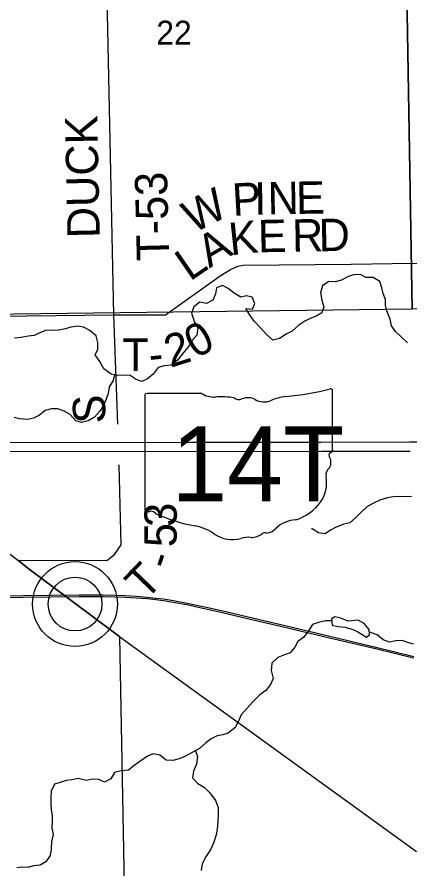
# Model space of a CAD drawing. Extents: x 0 to 34, y 0 to 22.
# Drawn here: x 2.754 to 3.443, y 18.256 to 19.751 of the extents above; entities that cross this region are included whole.
import ezdxf

# ---------------------------------------------------------------- set-up
doc = ezdxf.new("R2010")
doc.units = 0
for name, color, linetype in [('GM_X_County_Road', 7, 'Continuous'), ('GM_X_Minor_Lake', 7, 'Continuous'), ('GM_X_Minor_River', 7, 'Continuous'), ('GM_X_Rail_Line', 7, 'Continuous'), ('GM_X_Section', 7, 'Continuous'), ('GM_X_Section_Text', 7, 'Continuous'), ('GM_X_State_Location', 7, 'Continuous'), ('GM_X_State_Route', 7, 'Continuous'), ('GM_X_State_Shield', 7, 'Continuous'), ('GM_X_Township_Road', 7, 'Continuous'), ('GM_X_Township_Road_Text', 7, 'Continuous'), ('GM_X_Unincorporated', 7, 'Continuous'), ('GM_X_Unincorporated_Location', 7, 'Continuous')]:
    doc.layers.add(name, color=color, linetype=linetype)

msp = doc.modelspace()

# ---------------------------------------------------------------- linework, layer by layer
at = {"layer": 'GM_X_County_Road'}
msp.add_line((2.1794, 19.2202), (2.9238, 19.2285), dxfattribs=at)
at = {"layer": 'GM_X_Minor_Lake'}
for points in [[(3.3519, 18.6725), (3.3671, 18.6628), (3.3724, 18.6674), (3.3719, 18.6765), (3.3631, 18.687), (3.3525, 18.6926), (3.3347, 18.6913), (3.3221, 18.6965), (3.3115, 18.6984), (3.3059, 18.6949), (3.3071, 18.6843), (3.3166, 18.6817), (3.3302, 18.6807)], [(3.3302, 18.6807), (3.3347, 18.6791), (3.3395, 18.6777), (3.3448, 18.6758), (3.3495, 18.6737), (3.3519, 18.6725)]]:
    msp.add_lwpolyline(points, dxfattribs=at)
at = {"layer": 'GM_X_Minor_River'}
for points in [[(3.4392, 19.1791), (3.4281, 19.19), (3.4182, 19.1994), (3.4113, 19.2092), (3.4085, 19.2209), (3.4027, 19.2357), (3.4003, 19.2456), (3.4006, 19.2554), (3.3964, 19.266), (3.394, 19.2759), (3.3905, 19.2869), (3.3787, 19.294), (3.3662, 19.2939), (3.3567, 19.2991), (3.3449, 19.2986), (3.3351, 19.2955), (3.3231, 19.289), (3.3121, 19.2862), (3.3011, 19.2869), (3.2899, 19.2792), (3.2866, 19.2678), (3.289, 19.2541), (3.2921, 19.2427), (3.2888, 19.2317), (3.2786, 19.2259), (3.2684, 19.222), (3.2586, 19.2174), (3.2485, 19.2101), (3.2365, 19.1997), (3.2259, 19.1947), (3.2142, 19.187), (3.2025, 19.1842), (3.1911, 19.1944), (3.1815, 19.2053), (3.17, 19.2174), (3.1616, 19.2287), (3.1554, 19.2393), (3.1668, 19.2382), (3.1709, 19.2485), (3.1662, 19.2595), (3.1564, 19.2617), (3.1466, 19.2593), (3.1347, 19.2665), (3.1245, 19.2747), (3.1142, 19.2796), (3.1036, 19.2757), (3.1018, 19.265), (3.0974, 19.254), (3.0861, 19.2482), (3.0747, 19.2504), (3.0642, 19.2423), (3.0601, 19.2313), (3.0652, 19.2154), (3.0713, 19.2055), (3.0692, 19.1926), (3.0606, 19.1827), (3.0546, 19.1727), (3.0441, 19.1597), (3.0351, 19.149), (3.0246, 19.1402), (3.0118, 19.1389), (3.0016, 19.1358), (2.9926, 19.1243), (2.9824, 19.1159), (2.9726, 19.1113), (2.9628, 19.115), (2.9521, 19.1221), (2.9407, 19.1224), (2.9294, 19.1219), (2.9191, 19.1241), (2.9062, 19.1339), (2.8989, 19.1463), (2.8908, 19.158), (2.8953, 19.1683), (2.8955, 19.1797), (2.8928, 19.1915), (2.8813, 19.2009), (2.8703, 19.2068), (2.8608, 19.2083), (2.8483, 19.2067), (2.8385, 19.2039), (2.8264, 19.2015), (2.8158, 19.2011), (2.8052, 19.2014), (2.795, 19.1975), (2.7837, 19.1921), (2.7731, 19.1908), (2.761, 19.1888), (2.7489, 19.1876)], [(2.9247, 19.1229), (2.9226, 19.1131), (2.9156, 19.1024), (2.9134, 19.0903), (2.9101, 19.0803), (2.9053, 19.0693), (2.8989, 19.0594), (2.8899, 19.0487), (2.8783, 19.0425), (2.8669, 19.0393), (2.8567, 19.0423), (2.8471, 19.0536), (2.8365, 19.0596), (2.8251, 19.0637), (2.8141, 19.0636), (2.8031, 19.0604), (2.793, 19.0524), (2.7824, 19.047), (2.7718, 19.045), (2.7582, 19.046), (2.7487, 19.0482)], [(3.4459, 18.9095), (3.4349, 18.9094), (3.4243, 18.9097), (3.4141, 18.9092), (3.4042, 18.9072), (3.3906, 18.9033), (3.3782, 18.8975), (3.3677, 18.8914), (3.3571, 18.8818), (3.3478, 18.8722), (3.3376, 18.8634), (3.3274, 18.861), (3.3138, 18.856), (3.3041, 18.8506), (3.2943, 18.844), (3.2829, 18.8462), (3.2715, 18.8529), (3.2703, 18.8529)], [(3.3062, 18.6917), (3.2953, 18.6918), (3.2828, 18.6886), (3.2726, 18.6851), (3.2652, 18.6744), (3.2569, 18.6633), (3.2468, 18.6553), (3.2416, 18.6457), (3.2334, 18.6354), (3.2232, 18.6323), (3.2115, 18.6273), (3.201, 18.6173), (3.1996, 18.6047), (3.2031, 18.5907), (3.1987, 18.5801), (3.1904, 18.5697), (3.1799, 18.5617), (3.1675, 18.5494), (3.1574, 18.5387), (3.1469, 18.5268), (3.1425, 18.5154), (3.1365, 18.5043), (3.1245, 18.4944), (3.1147, 18.492), (3.1048, 18.49), (3.0947, 18.4846), (3.0849, 18.4777), (3.074, 18.4677), (3.0623, 18.4612), (3.0484, 18.4539), (3.0382, 18.4496), (3.0269, 18.4468), (3.0155, 18.4471), (3.0041, 18.4561), (2.9927, 18.4583), (2.9829, 18.4544), (2.9694, 18.4448), (2.9592, 18.4379), (2.9494, 18.4298), (2.9366, 18.4286), (2.9249, 18.4255), (2.9185, 18.4148), (2.9072, 18.4086), (2.897, 18.4131), (2.886, 18.4137), (2.8758, 18.4117), (2.861, 18.415), (2.85, 18.413), (2.8398, 18.4118), (2.8296, 18.4079), (2.8194, 18.4052), (2.8135, 18.393), (2.8128, 18.3812), (2.8129, 18.371), (2.8138, 18.36), (2.815, 18.3501), (2.8155, 18.3398), (2.8148, 18.3285), (2.8172, 18.3167), (2.8143, 18.3049), (2.8137, 18.2909), (2.8119, 18.2798), (2.8044, 18.2691), (2.7942, 18.263), (2.7825, 18.2621), (2.7727, 18.259), (2.7628, 18.2597), (2.753, 18.2584)], [(3.4499, 18.651), (3.4395, 18.6539), (3.4296, 18.6572), (3.4187, 18.6567), (3.4077, 18.6544), (3.3963, 18.6584), (3.386, 18.6671), (3.3742, 18.6712), (3.3722, 18.6712)], [(3.0667, 18.4637), (3.0707, 18.454), (3.0686, 18.4404), (3.0634, 18.4282), (3.0616, 18.416), (3.0712, 18.4062), (3.0826, 18.3991), (3.0921, 18.3897), (3.1021, 18.3765), (3.1068, 18.3644), (3.1069, 18.3515), (3.1062, 18.3393), (3.1052, 18.3264), (3.1034, 18.3161), (3.099, 18.3032), (3.0938, 18.2914), (3.0856, 18.2791), (3.0789, 18.2654), (3.0771, 18.2536)]]:
    msp.add_lwpolyline(points, dxfattribs=at)
at = {"layer": 'GM_X_Rail_Line'}
for points in [[(2.1, 18.7305), (2.109, 18.7306), (2.2199, 18.7315), (2.2909, 18.7321), (2.5385, 18.7345), (2.6658, 18.7351), (2.8628, 18.737), (2.885, 18.7371), (2.9051, 18.7371), (2.9252, 18.7366), (2.9432, 18.736), (2.9628, 18.7349), (2.9815, 18.7334), (2.9975, 18.7316), (3.0109, 18.73), (3.0284, 18.7273), (3.0523, 18.7229), (3.0854, 18.7157), (3.1127, 18.7096), (3.1492, 18.701), (3.2266, 18.6828), (3.3027, 18.6648), (3.3835, 18.6457), (3.4502, 18.6294)], [(2.1, 18.7277), (2.109, 18.7278), (2.22, 18.7287), (2.291, 18.7293), (2.5385, 18.7317), (2.6658, 18.7323), (2.8628, 18.7342), (2.885, 18.7343), (2.9051, 18.7343), (2.9251, 18.7338), (2.9431, 18.7332), (2.9626, 18.7321), (2.9812, 18.7306), (2.9972, 18.7288), (3.0106, 18.7273), (3.028, 18.7245), (3.0517, 18.7201), (3.0848, 18.713), (3.1121, 18.7069), (3.1485, 18.6983), (3.2259, 18.6801), (3.302, 18.6621), (3.3829, 18.643), (3.4495, 18.6266)]]:
    msp.add_lwpolyline(points, dxfattribs=at)
at = {"layer": 'GM_X_Section'}
for points in [[(4.4904, 20.2497), (4.497, 19.2557), (3.4475, 19.2384), (3.4305, 20.2427)], [(3.4305, 20.2427), (3.4475, 19.2384), (2.4219, 19.2256), (2.4052, 20.2337)]]:
    msp.add_lwpolyline(points, close=True, dxfattribs=at)
at = {"layer": 'GM_X_State_Route'}
for p, q in [((2.5408, 18.9623), (2.7549, 18.7978)), ((2.9341, 18.6634), (3.4547, 18.2871))]:
    msp.add_line(p, q, dxfattribs=at)
for points in [[(3.4435, 19.0056), (3.6553, 19.0056), (3.8845, 19.0061), (4.1596, 19.0061), (4.3747, 19.0061), (4.4833, 19.0063), (4.6257, 19.0064), (4.836, 19.0077), (4.9952, 19.0069), (5.1872, 19.0079)], [(2.5272, 18.972), (2.5405, 18.9799), (2.559, 18.9878), (2.5794, 18.9942), (2.6031, 18.9999), (2.6253, 19.0033), (2.6524, 19.0044), (2.6855, 19.0045), (3.0584, 19.0051), (3.2872, 19.0053), (3.4435, 19.0056)], [(2.5408, 18.9623), (2.5572, 18.9723), (2.5755, 18.9799), (2.5961, 18.986), (2.6168, 18.9872), (2.6691, 18.989), (3.059, 18.9887), (3.2874, 18.989), (3.4437, 18.9894)], [(2.7549, 18.7978), (2.7692, 18.7867), (2.7725, 18.7843)], [(2.7725, 18.7843), (2.927, 18.6687), (2.9341, 18.6634)]]:
    msp.add_lwpolyline(points, dxfattribs=at)
at = {"layer": 'GM_X_State_Shield'}
for p, q in [((2.978, 19.087), (2.978, 18.8869)), ((3.0778, 19.0905), (2.9812, 19.0905)), ((3.3076, 18.9907), (3.3076, 19.0954)), ((3.3075, 18.9908), (3.3076, 18.9907))]:
    msp.add_line(p, q, dxfattribs=at)
for centre, major_axis, start_param, end_param in [((3.1902, 19.3633), (0.3495, 0), 4.814394, 5.042369), ((3.3039, 19.0958), (0.00367, 0), 6.141152, 7.989035), ((2.9818, 19.0874), (0.00382, 0), 1.712693, 3.28349), ((3.1007, 19.1137), (0.037, 0), 4.042523, 4.731795), ((3.113, 18.9781), (0.133, 0), 1.404758, 1.657858), ((3.1432, 19.0885), (0.0107, 0), 3.836095, 5.185415), ((3.1589, 19.0653), (0.0222, 0), 0.950623, 2.079405), ((3.2348, 19.0293), (0.0703, 0), 1.699011, 2.107814), ((3.1876, 19.0971), (0.0267, 0), 4.081561, 5.145723), ((3.3067, 18.983), (0.00568, 0), 1.883978, 3.671073), ((3.2706, 18.9698), (0.0341, 0), 5.934695, 6.695948), ((3.3037, 18.9903), (0.00393, 0), 5.05454, 6.418171), ((3.3207, 18.9469), (0.0248, 0), 2.387724, 3.262537), ((3.2098, 18.9336), (0.0874, 0), 5.101752, 6.440018), ((2.9818, 18.8865), (0.00385, 0), 3.00124, 4.508301), ((2.9824, 18.9069), (0.0294, 0), 4.665946, 4.897461), ((2.9884, 18.8753), (0.0106, 0), 0.519207, 1.627899), ((3.1222, 19.0551), (0.2524, 0), 4.195997, 4.488961), ((3.047, 18.797), (0.079, 0), 0.823519, 1.323587), ((3.2466, 18.8307), (0.0479, 0), 1.647645, 2.488434), ((3.1324, 18.8744), (0.0501, 0), 4.026481, 4.996735), ((3.165, 18.8594), (0.0267, 0), 4.691044, 5.507374), ((3.1892, 18.84), (0.00752, 0), 1.147584, 2.315152), ((3.186, 18.8675), (0.0282, 0), 4.937069, 5.64225), ((3.1613, 18.8052), (0.0412, 0), 1.495662, 1.94098)]:
    msp.add_ellipse(centre, major_axis=major_axis, ratio=0.8, start_param=start_param, end_param=end_param, dxfattribs=at)
at = {"layer": 'GM_X_Township_Road'}
for p, q in [((2.9238, 19.2285), (2.9018, 20.2384)), ((2.9306, 19.0364), (2.9238, 19.2285)), ((2.9425, 18.2267), (2.9341, 18.6634))]:
    msp.add_line(p, q, dxfattribs=at)
for points in [[(2.9238, 19.2285), (3.0142, 19.2286), (3.1101, 19.2967), (3.1285, 19.308), (3.1414, 19.314), (3.1508, 19.3153), (3.3403, 19.3173), (3.4121, 19.3185), (3.4598, 19.3189), (3.5087, 19.3169), (3.5604, 19.3146), (3.5753, 19.3142), (3.5864, 19.3122), (3.6002, 19.3071), (3.6132, 19.3008), (3.6432, 19.2814), (3.6771, 19.2594), (3.6937, 19.2487), (3.7025, 19.2457)], [(2.7549, 18.7978), (2.9111, 18.7975), (2.925, 18.8083), (2.9366, 18.8248), (2.9331, 18.9653)], [(2.7725, 18.7843), (2.7692, 18.7867), (2.7549, 18.7978)], [(2.9341, 18.6634), (2.927, 18.6687), (2.7725, 18.7843)]]:
    msp.add_lwpolyline(points, dxfattribs=at)
at = {"layer": 'GM_X_Unincorporated'}
for radius in [0.0744, 0.0472]:
    msp.add_circle((2.8554, 18.7211), radius, dxfattribs=at)
at = {"layer": 'GM_X_Unincorporated_Location'}
msp.add_line((2.8554, 18.7211), (2.8554, 18.7211), dxfattribs=at)

# ---------------------------------------------------------------- texts
at = {"layer": 'GM_X_Section_Text'}
msp.add_text('22', height=0.04186, rotation=0, dxfattribs=at).set_placement((2.9981, 19.7025))
at = {"layer": 'GM_X_State_Location'}
for s in ['s', 'r']:
    msp.add_text(s, height=0.000189, dxfattribs=at).set_placement((3.1391, 18.9736))
msp.add_text('14T', height=0.000189, rotation=0, dxfattribs=at).set_placement((3.0697, 18.9599))
at = {"layer": 'GM_X_State_Shield'}
msp.add_text('14T', height=0.13184, dxfattribs=at).set_placement((3.0244, 18.901))
at = {"layer": 'GM_X_Township_Road_Text'}
for s, height, rotation, p in [('DUCK', 0.05682, 91.2131, (2.899, 19.3633)), ('T-53', 0.05682, 91.415, (3.0208, 19.3237)), ('P', 0.0568, 3.1922, (3.1328, 19.4019)), ('I', 0.0568, 0.9563, (3.1705, 19.4041)), ('N', 0.0568, 0.9545, (3.1939, 19.4044)), ('E', 0.0568, 0.953, (3.2438, 19.4053)), ('W', 0.0568, 26.9387, (3.0629, 19.3704)), ('R', 0.0568, 0.9387, (3.2369, 19.3391)), ('D', 0.0568, 0.9397, (3.2835, 19.3398)), ('K', 0.0568, 6.1079, (3.1285, 19.3327)), ('E', 0.0568, 1.0779, (3.1769, 19.338)), ('A', 0.0568, 29.9604, (3.0911, 19.3097)), ('L', 0.0568, 34.6529, (3.0572, 19.2862)), ('0', 0.0568, 29.0194, (3.0677, 19.1507)), ('T', 0.0568, 0, (2.9385, 19.1301)), ('2', 0.0568, 17.4117, (3.0228, 19.1353)), ('-', 0.0568, 5.8039, (2.9873, 19.1304)), ('S', 0.0568, 91.2447, (2.909, 19.0383)), ('3', 0.0568, 90.248, (3.0341, 18.8566)), ('5', 0.0568, 89.3159, (3.0337, 18.8206)), ('-', 0.0568, 70.8551, (3.0226, 18.7789)), ('T', 0.0568, 46.2153, (2.9794, 18.7257))]:
    msp.add_text(s, height=height, rotation=rotation, dxfattribs=at).set_placement(p)

doc.saveas('drawing.dxf')
